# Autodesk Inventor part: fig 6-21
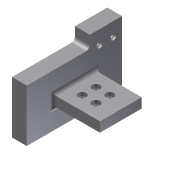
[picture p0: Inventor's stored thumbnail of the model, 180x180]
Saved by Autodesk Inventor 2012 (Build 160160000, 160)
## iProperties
Created: 2004-05
Part Number: fig 6-21
Document SubType Name: Modeling
Designer: CADCIM Technologies
Manufacturer: Standard
Standards Organization: Custom
Density: 1 g/cm^3
Material: Default
Author: CADCIM Technologies
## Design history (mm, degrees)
node "Sketch1"
sketch "Sketch2"
  geometry: L1 (0, 0)-(0, 26.557); L2 (0, 26.557)-(31.986, 26.557); L3 (31.986, 26.557)-(31.986, 32.916); L4 (31.986, 32.916)-(48.42, 32.916); L5 (48.42, 32.916)-(48.42, 0); L6 (48.42, 0)-(0, 0)
  constraints: 12 end point, 4 parallel, 1 perpendicular, 1 vertical
extrude "Extrusion1" new body sketch "Sketch2" distance "d0" = 7.5; taper "d1" = 0 deg
workplane "Work Plane1"
sketch "Sketch3"
  geometry: L1 (7.5, 35.088)-(30.78, 35.088); L2 (30.78, 35.088)-(30.78, 13.871); L3 (30.78, 13.871)-(7.5, 13.871); L4 (7.5, 31.986)-(7.5, 48.42) reference; L5 (7.5, 0)-(7.5, 31.986) reference
  constraints: 6 end point, 2 point on line, 1 horizontal, 1 parallel, 1 perpendicular
extrude "Extrusion2" join sketch "Sketch3" distance "d3" = 5; taper "d4" = 0 deg
fillet "Fillet2" dims "d7" = 2
fillet "Fillet3" dims "d8" = 2
hole "Hole1" diameter "d11" = 3; stored, may be unused: countersink angle "d15" = 90 deg, drill point angle "d17" = 118 deg; dims "d9" = 7, "d10" = 16, "d12" = 6, "d13" = 4, "d14" = 2, "d16" = 8
pattern_linear "Rectangular Pattern1" dims "d20" = 7, "d23" = 7
hole "Hole2" diameter "d26" = 2; stored, may be unused: countersink angle "d30" = 90 deg, drill point angle "d32" = 118 deg; dims "d24" = 5, "d25" = 7, "d27" = 6, "d28" = 3, "d29" = 1, "d31" = 8
pattern_linear "Rectangular Pattern2" dims "d35" = 7
body "Solid1"
other parameters: "d2" = -11
